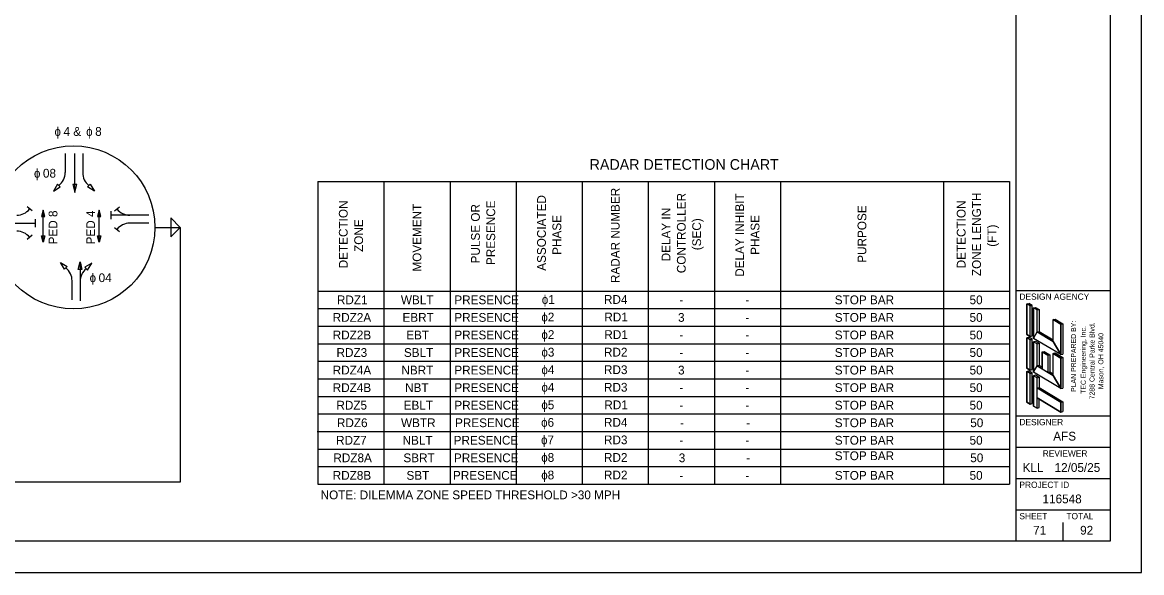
# Model space of a CAD drawing. Extents: x 5.5 to 39.5, y -2.1 to 19.9.
# Drawn here: x 21.69 to 39.55, y -2.09 to 6.69 of the extents above; entities that cross this region are included whole.
import ezdxf

# ---------------------------------------------------------------- set-up
doc = ezdxf.new("R2010")
doc.units = 0
for name, color, linetype in [('Default', 7, 'Continuous'), ('DR_X_Cells', 7, 'Continuous'), ('SC_Scratch1', 7, 'Continuous'), ('UT_P_Water_Cells', 7, 'Continuous'), ('UT_X_Misc_Cells', 7, 'Continuous')]:
    doc.layers.add(name, color=color, linetype=linetype)

msp = doc.modelspace()

# ---------------------------------------------------------------- linework, layer by layer
at = {"layer": 'Default'}
for p, q in [((26.406, 4.147), (37.441, 4.147)), ((26.406, 4.147), (26.406, -0.678)), ((27.46, 4.147), (27.46, -0.679)), ((28.514, 4.147), (28.514, -0.679)), ((29.568, 4.147), (29.568, -0.679)), ((30.623, 4.147), (30.623, -0.679)), ((31.677, 4.147), (31.677, -0.678)), ((32.731, 4.147), (32.731, -0.678)), ((33.785, 4.147), (33.785, -0.678)), ((36.387, 4.147), (36.387, -0.678)), ((37.441, 4.147), (37.441, -0.678)), ((26.406, 2.401), (37.441, 2.401)), ((26.406, 2.121), (37.441, 2.121)), ((26.406, 1.841), (37.441, 1.841)), ((26.406, 1.561), (37.441, 1.561)), ((26.406, 1.281), (37.441, 1.281)), ((26.406, 1.001), (37.441, 1.001)), ((26.406, 0.721), (37.441, 0.721)), ((26.406, 0.441), (37.441, 0.441)), ((26.395, 0.162), (37.441, 0.162)), ((26.406, -0.118), (37.441, -0.118)), ((26.406, -0.398), (37.441, -0.398)), ((26.406, -0.678), (37.441, -0.678))]:
    msp.add_line(p, q, dxfattribs=at)
at = {"layer": 'DR_X_Cells'}
msp.add_lwpolyline([(5.548, -2.088), (39.548, -2.088), (39.548, 19.912), (5.548, 19.912)], close=True, dxfattribs=at)
at = {"layer": 'SC_Scratch1'}
for p, q in [((37.548, -1.588), (37.548, 19.412)), ((37.548, 2.412), (39.048, 2.412)), ((37.548, 0.412), (39.048, 0.412)), ((37.548, -0.088), (39.048, -0.088)), ((37.548, -0.588), (39.048, -0.588)), ((37.548, -1.088), (39.048, -1.088))]:
    msp.add_line(p, q, dxfattribs=at)
msp.add_lwpolyline([(7.048, 19.412), (39.048, 19.412), (39.048, -1.588), (7.048, -1.588)], close=True, dxfattribs=at)
at = {"layer": 'UT_P_Water_Cells'}
for p, q in [((22.373, 4.596), (22.373, 4.29)), ((22.527, 3.973), (22.527, 4.596)), ((22.653, 4.596), (22.653, 4.29)), ((21.847, 3.678), (21.767, 3.742)), ((22.024, 3.179), (22.024, 3.692)), ((22.918, 3.179), (22.918, 3.692)), ((23.11, 3.547), (23.11, 3.674)), ((23.711, 3.611), (23.11, 3.611)), ((23.159, 3.678), (23.239, 3.742)), ((23.711, 3.611), (23.405, 3.611)), ((21.295, 3.484), (21.896, 3.484)), ((21.896, 3.547), (21.896, 3.421)), ((23.159, 3.417), (23.239, 3.353)), ((23.711, 3.484), (23.405, 3.484)), ((21.847, 3.29), (21.767, 3.226)), ((22.611, 2.869), (22.611, 2.246)), ((22.484, 2.259), (22.484, 2.564)), ((38.298, 1.412), (38.298, 1.412)), ((37.923, -1.413), (37.923, -1.413)), ((38.298, -1.588), (38.298, -1.288))]:
    msp.add_line(p, q, dxfattribs=at)
for points in [[(22.252, 4.106), (22.185, 3.995), (22.296, 4.062)], [(22.495, 4.098), (22.527, 3.973), (22.558, 4.098)], [(22.774, 4.106), (22.841, 3.995), (22.73, 4.062)], [(22.05, 3.588), (22.024, 3.692), (21.998, 3.588)], [(22.944, 3.588), (22.918, 3.692), (22.892, 3.588)], [(24.211, 3.417), (24.06, 3.568), (24.06, 3.265)], [(22.05, 3.283), (22.024, 3.179), (21.998, 3.283)], [(22.944, 3.283), (22.918, 3.179), (22.892, 3.283)], [(22.363, 2.749), (22.297, 2.859), (22.408, 2.793)], [(22.58, 2.744), (22.611, 2.869), (22.642, 2.744)], [(22.732, 2.736), (22.798, 2.847), (22.688, 2.78)]]:
    msp.add_lwpolyline(points, close=True, dxfattribs=at)
msp.add_lwpolyline([(23.805, 3.417), (24.211, 3.417), (24.211, -0.645), (8.045, -0.645), (7.639, -0.645), (7.639, 3.417), (8.045, 3.417)], dxfattribs=at)
msp.add_circle((22.506, 3.417), 1.3, dxfattribs=at)
for centre, start, end in [((22.108, 4.29), 308.7993, 0), ((22.918, 4.29), 180, 231.2007), ((21.6, 3.876), 270, 321.2007), ((23.405, 3.876), 218.7864, 269.9871), ((23.405, 3.219), 90.0129, 141.2136), ((21.6, 3.092), 38.7993, 90), ((22.219, 2.564), 360, 51.2007), ((22.876, 2.551), 128.7993, 178.779)]:
    msp.add_arc(centre, 0.265, start, end, dxfattribs=at)
at = {"layer": 'UT_X_Misc_Cells'}
for p, q in [((37.717, 2.197), (37.749, 2.205)), ((37.717, 1.711), (37.717, 2.197)), ((37.771, 2.165), (37.717, 2.197)), ((37.803, 2.173), (37.749, 2.205)), ((37.771, 2.165), (37.803, 2.173)), ((37.771, 1.679), (37.771, 2.165)), ((37.803, 1.687), (37.803, 2.173)), ((37.825, 2.132), (37.857, 2.14)), ((37.879, 2.1), (37.825, 2.132)), ((37.825, 1.646), (37.825, 2.132)), ((37.857, 2.14), (37.911, 2.108)), ((37.879, 2.1), (37.911, 2.108)), ((37.879, 1.749), (37.879, 2.1)), ((37.911, 2.108), (37.911, 1.757)), ((38.135, 1.946), (38.167, 1.954)), ((38.135, 1.595), (38.135, 1.946)), ((38.257, 1.873), (38.135, 1.946)), ((38.167, 1.954), (38.289, 1.881)), ((38.257, 1.873), (38.289, 1.881)), ((38.257, 1.387), (38.257, 1.873)), ((38.289, 1.881), (38.289, 1.395)), ((37.771, 1.679), (37.717, 1.711)), ((37.717, 1.657), (37.749, 1.665)), ((37.717, 1.171), (37.717, 1.657)), ((37.771, 1.625), (37.717, 1.657)), ((37.802, 1.634), (37.749, 1.665)), ((37.771, 1.679), (37.803, 1.687)), ((37.771, 1.625), (37.802, 1.634)), ((37.771, 1.139), (37.771, 1.625)), ((37.802, 1.148), (37.802, 1.634)), ((38.257, 1.387), (37.825, 1.646)), ((37.879, 1.749), (37.911, 1.757)), ((38.135, 1.595), (37.879, 1.749)), ((37.911, 1.757), (38.135, 1.623)), ((37.825, 1.592), (37.857, 1.6)), ((37.825, 1.106), (37.825, 1.592)), ((37.879, 1.56), (37.825, 1.592)), ((37.857, 1.6), (37.911, 1.568)), ((37.879, 1.56), (37.911, 1.568)), ((37.879, 1.209), (37.879, 1.56)), ((37.911, 1.568), (37.911, 1.217)), ((37.963, 1.431), (37.995, 1.439)), ((37.963, 1.431), (37.963, 1.158)), ((37.963, 1.431), (38.051, 1.378)), ((37.995, 1.439), (38.083, 1.386)), ((38.051, 1.378), (38.083, 1.386)), ((38.051, 1.378), (38.051, 1.106)), ((38.083, 1.386), (38.083, 1.114)), ((38.135, 1.406), (38.167, 1.414)), ((38.135, 1.055), (38.135, 1.406)), ((38.257, 1.333), (38.135, 1.406)), ((38.167, 1.414), (38.289, 1.341)), ((38.257, 1.387), (38.289, 1.395)), ((38.257, 1.333), (38.289, 1.341)), ((38.257, 0.847), (38.257, 1.333)), ((38.289, 1.341), (38.289, 0.855)), ((37.771, 1.139), (37.717, 1.171)), ((37.717, 1.117), (37.748, 1.127)), ((37.717, 0.631), (37.717, 1.117)), ((37.771, 1.085), (37.717, 1.117)), ((37.803, 1.093), (37.748, 1.127)), ((37.77, 1.085), (37.803, 1.093)), ((37.771, 1.139), (37.802, 1.148)), ((37.771, 0.599), (37.771, 1.085)), ((37.803, 0.607), (37.803, 1.093)), ((38.257, 0.847), (37.825, 1.106)), ((37.879, 1.209), (37.911, 1.217)), ((37.963, 1.158), (37.879, 1.209)), ((37.911, 1.217), (37.963, 1.186)), ((38.051, 1.106), (38.083, 1.114)), ((38.135, 1.055), (38.051, 1.106)), ((38.083, 1.114), (38.135, 1.083)), ((37.825, 1.052), (37.856, 1.063)), ((37.879, 1.02), (37.825, 1.052)), ((37.825, 0.566), (37.825, 1.052)), ((37.856, 1.063), (37.911, 1.028)), ((37.879, 1.02), (37.911, 1.028)), ((37.879, 0.856), (37.879, 1.02)), ((37.911, 1.028), (37.911, 0.864)), ((37.879, 0.856), (37.911, 0.864)), ((37.879, 0.856), (38.257, 0.629)), ((37.911, 0.864), (38.289, 0.637)), ((38.257, 0.847), (38.289, 0.855)), ((37.771, 0.599), (37.717, 0.631)), ((37.771, 0.599), (37.803, 0.607)), ((37.879, 0.534), (37.825, 0.566)), ((37.879, 0.698), (38.257, 0.471)), ((37.879, 0.534), (37.879, 0.698)), ((37.879, 0.534), (37.911, 0.542)), ((37.911, 0.542), (37.911, 0.679)), ((38.257, 0.629), (38.289, 0.637)), ((38.257, 0.471), (38.257, 0.629)), ((38.289, 0.637), (38.289, 0.48)), ((38.257, 0.471), (38.289, 0.48))]:
    msp.add_line(p, q, dxfattribs=at)
for points in [[(37.717, 1.711), (37.771, 1.679), (37.771, 2.165), (37.717, 2.197)], [(37.825, 1.646), (37.879, 1.749), (37.879, 2.1), (37.825, 2.132)], [(38.257, 1.387), (38.135, 1.595), (38.135, 1.946), (38.257, 1.873)], [(37.717, 1.171), (37.771, 1.139), (37.771, 1.625), (37.717, 1.657)], [(37.825, 1.646), (37.879, 1.749), (38.135, 1.595), (38.257, 1.387)], [(37.825, 1.106), (37.879, 1.209), (37.879, 1.56), (37.825, 1.592)], [(37.963, 1.158), (37.963, 1.431), (38.051, 1.378), (38.051, 1.106)], [(38.257, 0.847), (38.135, 1.055), (38.135, 1.406), (38.257, 1.333)], [(37.717, 0.631), (37.771, 0.599), (37.771, 1.085), (37.717, 1.117)], [(37.825, 1.106), (37.879, 1.209), (38.135, 1.055), (38.257, 0.847)], [(37.825, 0.566), (37.879, 0.534), (37.879, 1.02), (37.825, 1.052)], [(37.879, 0.698), (37.879, 0.856), (38.257, 0.629), (38.257, 0.471)]]:
    msp.add_lwpolyline(points, close=True, dxfattribs=at)

# ---------------------------------------------------------------- texts
at = {"layer": 'Default'}
for s, height, p in [('RADAR NUMBER', 0.14, (31.22, 2.529)), ('CONTROLLER', 0.14, (32.274, 2.686)), ('DELAY INHIBIT', 0.14, (33.205, 2.629)), ('ZONE LENGTH', 0.14, (36.984, 2.64)), ('DETECTION', 0.14, (26.881, 2.764)), ('MOVEMENT', 0.14, (28.057, 2.712)), ('PULSE OR', 0.14, (28.989, 2.842)), ('PRESENCE', 0.14, (29.234, 2.816)), ('ASSOCIATED', 0.14, (30.043, 2.725)), ('PURPOSE', 0.14, (35.156, 2.852)), ('DETECTION', 0.14, (36.739, 2.764)), ('PHASE', 0.14, (30.288, 2.979)), ('DELAY IN', 0.14, (32.029, 2.875)), ('PHASE', 0.14, (33.45, 2.979)), ('ZONE', 0.14, (27.126, 3.025)), ('(SEC)', 0.14, (32.519, 3.052)), ('(FT)', 0.14, (37.229, 3.108)), ('PLAN PREPARED BY:', 0.08, (38.501, 0.792)), ('TEC Engineering, Inc.', 0.08, (38.657, 0.762)), ('7288 Central Parke Blvd.', 0.08, (38.797, 0.674)), ('Mason, OH 45040', 0.08, (38.937, 0.836))]:
    msp.add_text(s, height=height, rotation=90, dxfattribs=at).set_placement(p)
for s, p in [('RDZ1', (26.709, 2.191)), ('WBLT', (27.73, 2.191)), ('PRESENCE', (28.583, 2.191)), ('ɸ1', (29.978, 2.197)), ('RD4', (30.97, 2.197)), ('STOP BAR', (34.652, 2.191)), ('50', (36.803, 2.191)), ('-', (32.173, 2.191)), ('-', (33.227, 2.191)), ('RDZ2A', (26.642, 1.911)), ('EBRT', (27.755, 1.911)), ('PRESENCE', (28.583, 1.911)), ('ɸ2', (29.971, 1.917)), ('RD1', (30.976, 1.917)), ('3', (32.152, 1.911)), ('-', (33.227, 1.911)), ('STOP BAR', (34.652, 1.911)), ('50', (36.803, 1.911)), ('RDZ2B', (26.642, 1.631)), ('EBT', (27.815, 1.631)), ('PRESENCE', (28.583, 1.631)), ('ɸ2', (29.971, 1.637)), ('RD1', (30.976, 1.637)), ('-', (32.173, 1.631)), ('-', (33.227, 1.631)), ('STOP BAR', (34.652, 1.631)), ('50', (36.803, 1.631)), ('RDZ3', (26.703, 1.351)), ('SBLT', (27.778, 1.351)), ('PRESENCE', (28.583, 1.351)), ('ɸ3', (29.972, 1.357)), ('RD2', (30.97, 1.357)), ('STOP BAR', (34.652, 1.351)), ('50', (36.803, 1.351)), ('-', (32.173, 1.351)), ('-', (33.227, 1.351)), ('RDZ4A', (26.642, 1.071)), ('NBRT', (27.738, 1.071)), ('PRESENCE', (28.583, 1.071)), ('ɸ4', (29.972, 1.077)), ('RD3', (30.97, 1.077)), ('3', (32.152, 1.071)), ('-', (33.227, 1.071)), ('STOP BAR', (34.652, 1.071)), ('50', (36.803, 1.071)), ('RDZ4B', (26.642, 0.791)), ('NBT', (27.797, 0.791)), ('PRESENCE', (28.583, 0.791)), ('ɸ4', (29.972, 0.797)), ('RD3', (30.97, 0.797)), ('STOP BAR', (34.652, 0.791)), ('50', (36.803, 0.791)), ('-', (32.173, 0.791)), ('-', (33.227, 0.791)), ('RDZ5', (26.701, 0.511)), ('EBLT', (27.774, 0.511)), ('PRESENCE', (28.583, 0.511)), ('ɸ5', (29.97, 0.517)), ('RD1', (30.976, 0.517)), ('-', (32.173, 0.511)), ('-', (33.227, 0.511)), ('STOP BAR', (34.652, 0.511)), ('50', (36.803, 0.511)), ('RDZ6', (26.709, 0.231)), ('WBTR', (27.732, 0.231)), ('PRESENCE', (28.594, 0.231)), ('ɸ6', (29.967, 0.237)), ('RD4', (30.97, 0.237)), ('STOP BAR', (34.652, 0.231)), ('50', (36.814, 0.231)), ('-', (32.184, 0.231)), ('-', (33.238, 0.231)), ('RDZ7', (26.696, -0.048)), ('NBLT', (27.757, -0.048)), ('PRESENCE', (28.572, -0.048)), ('ɸ7', (29.965, -0.042)), ('RD3', (30.97, -0.042)), ('-', (32.173, -0.048)), ('-', (33.227, -0.048)), ('STOP BAR', (34.652, -0.048)), ('50', (36.803, -0.048)), ('ɸ8', (29.969, -0.322)), ('STOP BAR', (34.652, -0.295)), ('RDZ8A', (26.653, -0.328)), ('SBRT', (27.77, -0.328)), ('PRESENCE', (28.577, -0.328)), ('RD2', (30.97, -0.322)), ('3', (32.163, -0.328)), ('-', (33.238, -0.328)), ('50', (36.814, -0.328)), ('RDZ8B', (26.642, -0.608)), ('SBT', (27.819, -0.608)), ('PRESENCE', (28.561, -0.608)), ('ɸ8', (29.969, -0.602)), ('RD2', (30.97, -0.602)), ('STOP BAR', (34.652, -0.608)), ('50', (36.803, -0.608)), ('-', (32.173, -0.608)), ('-', (33.227, -0.608)), ('NOTE: DILEMMA ZONE SPEED THRESHOLD >30 MPH', (26.449, -0.919))]:
    msp.add_text(s, height=0.14, dxfattribs=at).set_placement(p)
at = {"layer": 'UT_P_Water_Cells'}
for s, height, p in [('DESIGN AGENCY', 0.1, (37.598, 2.262)), ('DESIGNER', 0.1, (37.598, 0.262)), ('AFS', 0.14, (38.138, 0.017)), ('REVIEWER', 0.1, (37.97, -0.238)), ('KLL', 0.14, (37.649, -0.483)), ('12/05/25', 0.14, (38.159, -0.483)), ('PROJECT ID', 0.1, (37.598, -0.738)), ('116548', 0.14, (37.967, -0.983)), ('SHEET', 0.1, (37.598, -1.238)), ('TOTAL', 0.1, (38.348, -1.238)), ('71', 0.14, (37.817, -1.483)), ('92', 0.14, (38.567, -1.483))]:
    msp.add_text(s, height=height, dxfattribs=at).set_placement(p)
at = {"layer": 'UT_X_Misc_Cells'}
for s, height, p in [('ɸ', 0.14, (22.203, 4.876)), ('4 & ', 0.14, (22.347, 4.876)), ('ɸ', 0.14, (22.708, 4.876)), ('8', 0.14, (22.852, 4.876)), ('RADAR DETECTION CHART ', 0.17, (30.741, 4.335)), ('ɸ', 0.14, (21.875, 4.21)), ('08', 0.14, (22.019, 4.21)), ('ɸ', 0.14, (22.763, 2.544)), ('04', 0.14, (22.907, 2.544))]:
    msp.add_text(s, height=height, dxfattribs=at).set_placement(p)
for s, p in [('PED 8', (22.25, 3.145)), ('PED 4', (22.85, 3.145))]:
    msp.add_text(s, height=0.14, rotation=90, dxfattribs=at).set_placement(p)

doc.saveas('drawing.dxf')
